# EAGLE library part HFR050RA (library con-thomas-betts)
THOMAS&BETTS
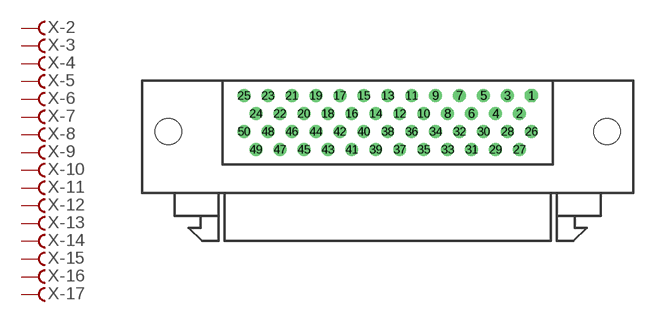
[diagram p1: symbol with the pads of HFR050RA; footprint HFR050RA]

Designator prefix X; gates -2=F -3=F -4=F -5=F -6=F -7=F -8=F -9=F -10=F -11=F -12=F -13=F -14=F -15=F -16=F -17=F -18=F -19=F -20=F -21=F -22=F -23=F -24=F -25=F -27=F -28=F -29=F -30=F -31=F -32=F -33=F -34=F -35=F -36=F -37=F -38=F -39=F -40=F -41=F -42=F -43=F -44=F -45=F -46=F -47=F -48=F -49=F -50=F -1=FV -26=F

## HFR050RA  [HFR050RA]
1  -1:F  pas
2  -2:F  pas
3  -3:F  pas
4  -4:F  pas
5  -5:F  pas
6  -6:F  pas
7  -7:F  pas
8  -8:F  pas
9  -9:F  pas
10  -10:F  pas
11  -11:F  pas
12  -12:F  pas
13  -13:F  pas
14  -14:F  pas
15  -15:F  pas
16  -16:F  pas
17  -17:F  pas
18  -18:F  pas
19  -19:F  pas
20  -20:F  pas
21  -21:F  pas
22  -22:F  pas
23  -23:F  pas
24  -24:F  pas
25  -25:F  pas
26  -26:F  pas
27  -27:F  pas
28  -28:F  pas
29  -29:F  pas
30  -30:F  pas
31  -31:F  pas
32  -32:F  pas
33  -33:F  pas
34  -34:F  pas
35  -35:F  pas
36  -36:F  pas
37  -37:F  pas
38  -38:F  pas
39  -39:F  pas
40  -40:F  pas
41  -41:F  pas
42  -42:F  pas
43  -43:F  pas
44  -44:F  pas
45  -45:F  pas
46  -46:F  pas
47  -47:F  pas
48  -48:F  pas
49  -49:F  pas
50  -50:F  pas

## Footprint HFR050RA (pad centres in mm)
THOMAS&BETTS
drill 0.864 octagon: 1 15.24,8.89
drill 0.864 round: 2 13.97,6.985; 3 12.7,8.89; 4 11.43,6.985; 5 10.16,8.89; 6 8.89,6.985; 7 7.62,8.89; 8 6.35,6.985; 9 5.08,8.89; 10 3.81,6.985; 11 2.54,8.89; 12 1.27,6.985; 13 0,8.89; 14 -1.27,6.985; 15 -2.54,8.89; 16 -3.81,6.985; 17 -5.08,8.89; 18 -6.35,6.985; 19 -7.62,8.89; 20 -8.89,6.985; 21 -10.16,8.89; 22 -11.43,6.985; 23 -12.7,8.89; 24 -13.97,6.985; 25 -15.24,8.89; 26 15.24,5.08; 27 13.97,3.175; 28 12.7,5.08; 29 11.43,3.175; 30 10.16,5.08; 31 8.89,3.175; 32 7.62,5.08; 33 6.35,3.175; 34 5.08,5.08; 35 3.81,3.175; 36 2.54,5.08; 37 1.27,3.175; 38 0,5.08; 39 -1.27,3.175; 40 -2.54,5.08; 41 -3.81,3.175; 42 -5.08,5.08; 43 -6.35,3.175; 44 -7.62,5.08; 45 -8.89,3.175; 46 -10.16,5.08; 47 -11.43,3.175; 48 -12.7,5.08; 49 -13.97,3.175; 50 -15.24,5.08
hole 2.769 at 23.241,5.08
hole 2.769 at -23.241,5.08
